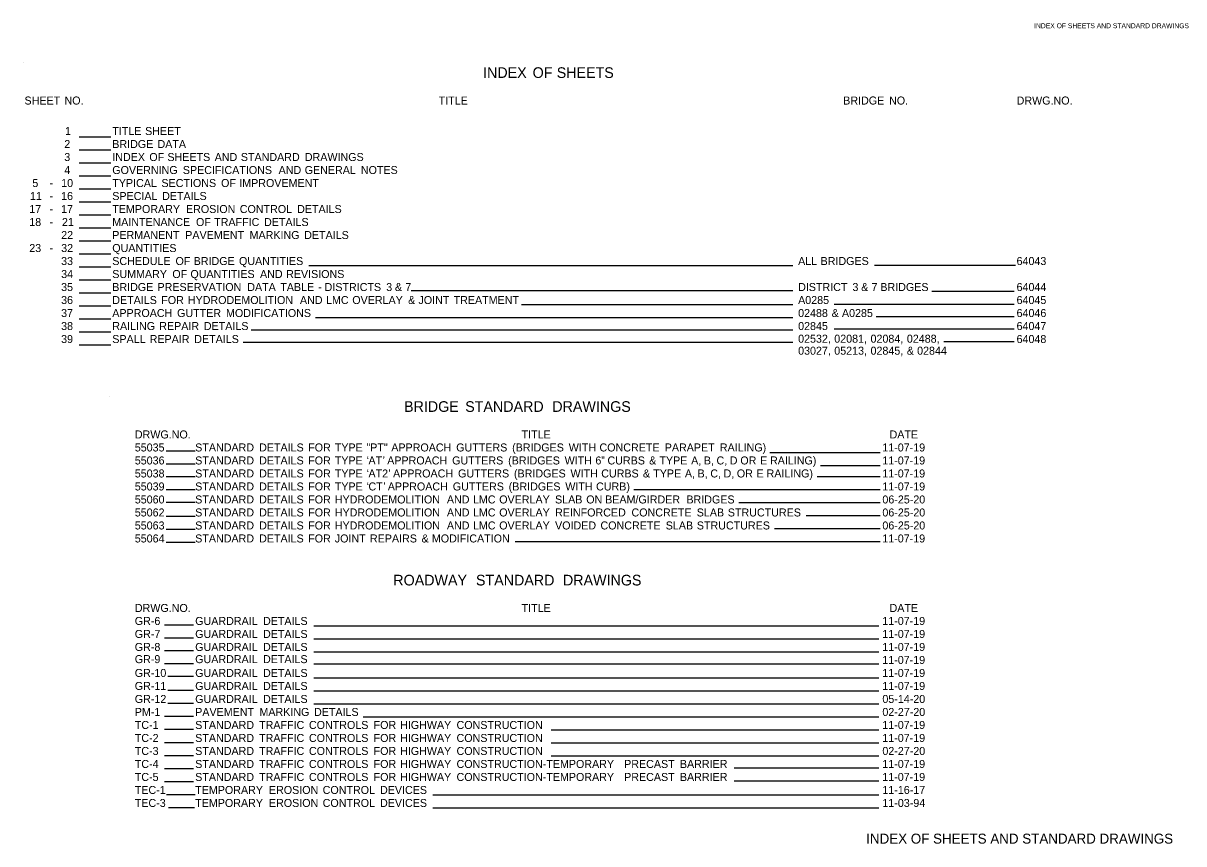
# Model space of a CAD drawing. Extents: x 1930541 to 1931933, y 596452 to 598974.
import ezdxf

# ---------------------------------------------------------------- set-up
doc = ezdxf.new("R2010")
doc.units = 0
for name, color, linetype in [('Default', 7, 'Continuous'), ('R_Border', 7, 'Continuous'), ('R_Border Prem', 7, 'Continuous')]:
    doc.layers.add(name, color=color, linetype=linetype)

msp = doc.modelspace()

# ---------------------------------------------------------------- linework, layer by layer
at = {"layer": 'Default'}
for p, q in [((1930540.8, 598926.7), (1930540.8, 598926.7)), ((1930607.9, 598837.7), (1930646.1, 598837.7)), ((1930607.9, 598822.1), (1930646.1, 598822.1)), ((1930607.9, 598806.5), (1930646.1, 598806.5)), ((1930607.9, 598790.9), (1930646.1, 598790.9)), ((1930607.9, 598775.3), (1930646.1, 598775.3)), ((1930607.9, 598759.7), (1930646.1, 598759.7)), ((1930607.9, 598744.1), (1930646.1, 598744.1)), ((1930607.9, 598728.5), (1930646.1, 598728.5)), ((1930607.9, 598712.9), (1930646.1, 598712.9)), ((1930607.9, 598697.3), (1930646.1, 598697.3)), ((1930607.9, 598681.7), (1930646.1, 598681.7)), ((1931464.1, 598682.7), (1930883.6, 598682.7)), ((1931731.5, 598683), (1931562.4, 598683)), ((1930607.9, 598666.1), (1930646.1, 598666.1)), ((1930607.9, 598650.5), (1930646.1, 598650.5)), ((1931464.1, 598652.8), (1931006.3, 598652.8)), ((1931729.7, 598651.8), (1931631.2, 598651.8)), ((1931464.1, 598635.9), (1931138.6, 598635.9)), ((1931729.7, 598636.2), (1931514, 598636.2)), ((1930607.9, 598634.9), (1930646.1, 598634.9)), ((1930607.9, 598619.3), (1930646.1, 598619.3)), ((1931464.1, 598620.3), (1930891.7, 598620.3)), ((1931729.7, 598621.4), (1931564.2, 598621.4)), ((1930607.9, 598603.7), (1930646.1, 598603.7)), ((1931464.1, 598605.5), (1930814.4, 598605.5)), ((1931729.7, 598606.6), (1931514, 598606.6)), ((1930607.9, 598588.1), (1930646.1, 598588.1)), ((1931464.1, 598590.7), (1930804.8, 598590.7)), ((1931729.7, 598591.7), (1931645.5, 598591.7)), ((1930644.2, 598526), (1930644.2, 598526)), ((1930747.2, 598460.3), (1930712.5, 598460.3)), ((1931436.8, 598458.9), (1931569.1, 598458.9)), ((1930747.2, 598444.9), (1930712.5, 598444.9)), ((1931497.4, 598443.3), (1931569.1, 598443.3)), ((1930747.2, 598429.5), (1930712.5, 598429.5)), ((1931493.3, 598430), (1931569.1, 598430)), ((1930747.2, 598414.1), (1930712.5, 598414.1)), ((1931273.4, 598414.4), (1931569.1, 598414.4)), ((1930747.2, 598398.7), (1930712.5, 598398.7)), ((1931399.5, 598398.8), (1931569.1, 598398.8)), ((1930747.2, 598382.1), (1930712.5, 598382.1)), ((1931480.1, 598383.2), (1931569.1, 598383.2)), ((1930747.2, 598366.3), (1930712.5, 598366.3)), ((1931442.3, 598367.6), (1931569.1, 598367.6)), ((1930747.2, 598350.7), (1930712.5, 598350.7)), ((1931131.2, 598352), (1931569.1, 598352)), ((1930745, 598251.4), (1930710.2, 598251.4)), ((1930889.7, 598250.7), (1931567.4, 598250.7)), ((1930745, 598236), (1930710.2, 598236)), ((1930889.7, 598235.1), (1931567.4, 598235.1)), ((1930745, 598220.6), (1930710.2, 598220.6)), ((1930889.7, 598219.5), (1931567.4, 598219.5)), ((1930745, 598205.2), (1930710.2, 598205.2)), ((1930889.7, 598205), (1931567.4, 598205)), ((1930745, 598189.8), (1930714.2, 598189.8)), ((1930889.7, 598188.3), (1931567.4, 598188.3)), ((1930745, 598173.2), (1930714.2, 598173.2)), ((1930889.7, 598172.7), (1931567.4, 598172.7)), ((1930745, 598157.4), (1930714.2, 598157.4)), ((1930889.7, 598157.1), (1931567.4, 598157.1)), ((1930745, 598141.8), (1930710.2, 598141.8)), ((1930948.6, 598141.5), (1931567.4, 598141.5)), ((1930745, 598126.2), (1930710.2, 598126.2)), ((1931174.1, 598125.9), (1931567.4, 598125.9)), ((1930745, 598110.5), (1930710.2, 598110.5)), ((1931020.8, 598115), (1931020.8, 598115)), ((1931174.1, 598110.3), (1931567.4, 598110.3)), ((1930745, 598094.9), (1930710.2, 598094.9)), ((1931174.1, 598094.7), (1931567.4, 598094.7)), ((1930745, 598079.2), (1930710.2, 598079.2)), ((1931393.9, 598080.3), (1931567.4, 598080.3)), ((1930745, 598063.5), (1930710.2, 598063.5)), ((1931393.9, 598064.7), (1931567.4, 598064.7)), ((1930747.3, 598047.9), (1930712.6, 598047.9)), ((1931032.4, 598047.9), (1931567.4, 598047.9)), ((1930746.4, 598032.2), (1930715, 598032.2)), ((1931032.4, 598032.3), (1931567.4, 598032.3))]:
    msp.add_line(p, q, dxfattribs=at)

# ---------------------------------------------------------------- texts
for s, height, p in [('INDEX', 12.8, (1931092.6, 598908.2)), (' OF', 12.8, (1931147.3, 598908.2)), (' SHEETS', 12.8, (1931176.2, 598908.2)), ('SHEET', 9.6, (1930542.4, 598876.3)), (' NO.', 9.6, (1930586.8, 598876.3)), ('TITLE', 9.6, (1931039.3, 598876.3)), ('BRIDGE', 9.6, (1931524.7, 598876.3)), (' NO.', 9.6, (1931576.2, 598876.3)), ('DRWG.NO.', 9.6, (1931732.8, 598876.3)), ('1', 9.6, (1930591, 598839.7)), ('TITLE', 9.6, (1930647.7, 598839.7)), (' SHEET', 9.6, (1930683.5, 598839.7)), ('2', 9.6, (1930590.1, 598824.1)), ('BRIDGE', 9.6, (1930647.7, 598824.1)), (' DATA', 9.6, (1930698.4, 598824.1)), ('3', 9.6, (1930590.1, 598808.5)), ('INDEX', 9.6, (1930647.7, 598808.5)), (' OF', 9.6, (1930688.6, 598808.5)), (' SHEETS', 9.6, (1930710.3, 598808.5)), (' AND', 9.6, (1930767, 598808.5)), (' STANDARD', 9.6, (1930798.4, 598808.5)), (' DRAWINGS', 9.6, (1930875.2, 598808.5)), ('4', 9.6, (1930590.1, 598792.9)), ('GOVERNING', 9.6, (1930647.7, 598792.9)), (' SPECIFICATIONS', 9.6, (1930728.8, 598792.9)), (' AND', 9.6, (1930843.7, 598792.9)), (' GENERAL', 9.6, (1930875, 598792.9)), (' NOTES', 9.6, (1930942.4, 598792.9)), ('5', 9.6, (1930551.8, 598777.3)), ('-', 9.6, (1930572.4, 598777.3)), ('10', 9.6, (1930586.4, 598777.3)), ('TYPICAL', 9.6, (1930647.7, 598777.3)), (' SECTIONS', 9.6, (1930703.1, 598777.3)), (' OF', 9.6, (1930774.7, 598777.3)), (' IMPROVEMENT', 9.6, (1930796.5, 598777.3)), ('11', 9.6, (1930549, 598761.7)), ('-', 9.6, (1930572.4, 598761.7)), ('16', 9.6, (1930586.3, 598761.7)), ('SPECIAL', 9.6, (1930647.7, 598761.7)), (' DETAILS', 9.6, (1930703.9, 598761.7)), ('17', 9.6, (1930548.1, 598746.1)), ('-', 9.6, (1930572.4, 598746.1)), ('17', 9.6, (1930586.3, 598746.1)), ('TEMPORARY', 9.6, (1930647.7, 598746.1)), (' EROSION', 9.6, (1930732.6, 598746.1)), (' CONTROL', 9.6, (1930797.1, 598746.1)), (' DETAILS', 9.6, (1930865.9, 598746.1)), ('18', 9.6, (1930548.1, 598730.5)), ('-', 9.6, (1930572.4, 598730.5)), ('21', 9.6, (1930587.3, 598730.5)), ('MAINTENANCE', 9.6, (1930647.7, 598730.5)), (' OF', 9.6, (1930744.6, 598730.5)), (' TRAFFIC', 9.6, (1930766.4, 598730.5)), (' DETAILS', 9.6, (1930826.2, 598730.5)), ('22', 9.6, (1930586.4, 598714.9)), ('PERMANENT', 9.6, (1930647.7, 598714.9)), (' PAVEMENT', 9.6, (1930731.7, 598714.9)), (' MARKING', 9.6, (1930808.9, 598714.9)), (' DETAILS', 9.6, (1930874.4, 598714.9)), ('23', 9.6, (1930548.1, 598699.3)), ('32', 9.6, (1930586.4, 598699.3)), ('QUANTITIES', 9.6, (1930647.7, 598699.3)), ('-', 9.6, (1930572.4, 598699.3)), ('33', 9.6, (1930586.3, 598683.7)), ('SCHEDULE', 9.6, (1930647.7, 598683.7)), (' OF', 9.6, (1930720, 598683.7)), (' BRIDGE', 9.6, (1930741.8, 598683.7)), (' QUANTITIES', 9.6, (1930796.2, 598683.7)), ('ALL', 9.6, (1931470.6, 598683.7)), (' BRIDGES', 9.6, (1931494, 598683.7)), ('64043', 9.6, (1931732.7, 598683.7)), ('34', 9.6, (1930586.4, 598668.1)), ('SUMMARY', 9.6, (1930647.7, 598668.1)), (' OF', 9.6, (1930716.2, 598668.1)), (' QUANTITIES', 9.6, (1930737.9, 598668.1)), (' AND', 9.6, (1930821.4, 598668.1)), (' REVISIONS', 9.6, (1930852.7, 598668.1)), ('35', 9.6, (1930586.3, 598652.5)), ('BRIDGE', 9.6, (1930647.7, 598652.5)), (' PRESERVATION', 9.6, (1930698.4, 598652.5)), (' DATA', 9.6, (1930806.1, 598652.5)), (' TABLE', 9.6, (1930845.7, 598652.5)), (' -', 9.6, (1930891.2, 598652.5)), (' DISTRICTS', 9.6, (1930898.9, 598652.5)), (' 3', 9.6, (1930972.8, 598652.5)), (' &', 9.6, (1930983.3, 598652.5)), (' 7', 9.6, (1930995.7, 598652.5)), ('DISTRICT', 9.6, (1931470.6, 598652.5)), (' 3', 9.6, (1931532.2, 598652.5)), (' &', 9.6, (1931542.7, 598652.5)), (' 7', 9.6, (1931555.1, 598652.5)), (' BRIDGES', 9.6, (1931565.7, 598652.5)), ('64044', 9.6, (1931732.7, 598652.5)), ('36', 9.6, (1930586.3, 598636.9)), ('DETAILS', 9.6, (1930647.7, 598636.9)), (' FOR', 9.6, (1930702.9, 598636.9)), (' HYDRODEMOLITION', 9.6, (1930734.8, 598636.9)), (' AND', 9.6, (1930869.3, 598636.9)), (' LMC', 9.6, (1930900.6, 598636.9)), (' OVERLAY', 9.6, (1930932.1, 598636.9)), (' &', 9.6, (1930999.1, 598636.9)), (' JOINT', 9.6, (1931011.5, 598636.9)), (' TREATMENT', 9.6, (1931053.7, 598636.9)), ('A0285', 9.6, (1931470.6, 598636.9)), ('64045', 9.6, (1931732.7, 598636.9)), ('37', 9.6, (1930586.3, 598621.3)), ('APPROACH', 9.6, (1930647.7, 598621.3)), (' GUTTER', 9.6, (1930721.9, 598621.3)), (' MODIFICATIONS', 9.6, (1930780.6, 598621.3)), ('02488', 9.6, (1931470.6, 598621.3)), (' &', 9.6, (1931507.3, 598621.3)), (' A0285', 9.6, (1931519.6, 598621.3)), ('64046', 9.6, (1931732.7, 598621.3)), ('38', 9.6, (1930586.3, 598605.7)), ('RAILING', 9.6, (1930647.7, 598605.7)), (' REPAIR', 9.6, (1930700.5, 598605.7)), (' DETAILS', 9.6, (1930754, 598605.7)), ('02845', 9.6, (1931470.6, 598605.7)), ('64047', 9.6, (1931732.7, 598605.7)), ('39', 9.6, (1930586.3, 598590.1)), ('SPALL', 9.6, (1930647.7, 598590.1)), (' REPAIR', 9.6, (1930689, 598590.1)), (' DETAILS', 9.6, (1930742.5, 598590.1)), ('02532,', 9.6, (1931470.6, 598590.5)), (' 02081,', 9.6, (1931510.4, 598590.5)), (' 02084,', 9.6, (1931553.9, 598590.5)), (' 02488,', 9.6, (1931597.5, 598590.5)), ('64048', 9.6, (1931732.7, 598590.1)), ('03027,', 9.6, (1931470.6, 598576.1)), (' 05213,', 9.6, (1931510.4, 598576.1)), (' 02845,', 9.6, (1931553.9, 598576.1)), (' &', 9.6, (1931597.5, 598576.1)), (' 02844', 9.6, (1931609.8, 598576.1))]:
    msp.add_text(s, height=height, rotation=360, dxfattribs=at).set_placement(p)
for s, height, p in [('BRIDGE', 12.8, (1930997.8, 598507.5)), (' STANDARD', 12.8, (1931066.4, 598507.5)), (' DRAWINGS', 12.8, (1931170.9, 598507.5)), ('DRWG.NO.', 9.6, (1930674.8, 598475.6)), ('TITLE', 9.6, (1931138.8, 598475.6)), ('DATE', 9.6, (1931580.3, 598475.6)), ('55035', 9.6, (1930674.7, 598460)), ('STANDARD', 9.6, (1930747.2, 598460)), (' DETAILS', 9.6, (1930820.3, 598460)), (' FOR', 9.6, (1930879.2, 598460)), (' TYPE', 9.6, (1930911.1, 598460)), (' "PT"', 9.6, (1930949.1, 598460)), (' APPROACH', 9.6, (1930978.9, 598460)), (' GUTTERS', 9.6, (1931056.8, 598460)), (' (BRIDGES', 9.6, (1931123.9, 598460)), (' WITH', 9.6, (1931191.8, 598460)), (' CONCRETE', 9.6, (1931228.7, 598460)), (' PARAPET', 9.6, (1931307, 598460)), (' RAILING)', 9.6, (1931373.1, 598460)), ('11-07-19', 9.6, (1931571.6, 598460)), ('55036', 9.6, (1930674.7, 598444.4)), ('STANDARD', 9.6, (1930747.2, 598444.4)), (' DETAILS', 9.6, (1930820.3, 598444.4)), (' FOR', 9.6, (1930879.2, 598444.4)), (' TYPE', 9.6, (1930911.1, 598444.4)), ('‘', 9.6, (1930952.8, 598444.4)), ('AT', 9.6, (1930955.1, 598444.4)), ('’', 9.6, (1930971.9, 598444.4)), (' APPROACH', 9.6, (1930974, 598444.4)), (' GUTTERS', 9.6, (1931051.9, 598444.4)), (' (BRIDGES', 9.6, (1931119.1, 598444.4)), (' WITH', 9.6, (1931186.9, 598444.4)), (' 6', 9.6, (1931223.8, 598444.4)), ('”', 9.6, (1931234.4, 598444.4)), (' CURBS', 9.6, (1931238.3, 598444.4)), (' &', 9.6, (1931288.3, 598444.4)), (' TYPE', 9.6, (1931300.6, 598444.4)), (' A,', 9.6, (1931338.7, 598444.4)), (' B,', 9.6, (1931353.9, 598444.4)), (' C,', 9.6, (1931369.1, 598444.4)), (' D', 9.6, (1931385, 598444.4)), (' OR', 9.6, (1931397.7, 598444.4)), (' E', 9.6, (1931421.4, 598444.4)), (' RAILING)', 9.6, (1931433.3, 598444.4)), ('11-07-19', 9.6, (1931571.6, 598444.4)), ('55038', 9.6, (1930674.7, 598428.8)), ('STANDARD', 9.6, (1930747.2, 598428.8)), (' DETAILS', 9.6, (1930820.3, 598428.8)), (' FOR', 9.6, (1930879.2, 598428.8)), (' TYPE', 9.6, (1930911.1, 598428.8)), ('‘', 9.6, (1930952.8, 598428.8)), ('AT2', 9.6, (1930955.1, 598428.8)), ('’', 9.6, (1930978.9, 598428.8)), (' APPROACH', 9.6, (1930981, 598428.8)), (' GUTTERS', 9.6, (1931059, 598428.8)), (' (BRIDGES', 9.6, (1931126.1, 598428.8)), (' WITH', 9.6, (1931193.9, 598428.8)), (' CURBS', 9.6, (1931230.8, 598428.8)), (' &', 9.6, (1931280.8, 598428.8)), (' TYPE', 9.6, (1931293.2, 598428.8)), (' A,', 9.6, (1931331.2, 598428.8)), (' B,', 9.6, (1931346.4, 598428.8)), (' C,', 9.6, (1931361.7, 598428.8)), (' D,', 9.6, (1931377.6, 598428.8)), (' OR', 9.6, (1931393.5, 598428.8)), (' E', 9.6, (1931417.2, 598428.8)), (' RAILING)', 9.6, (1931429.2, 598428.8)), ('11-07-19', 9.6, (1931571.6, 598428.8)), ('55039', 9.6, (1930674.7, 598413.2)), ('STANDARD', 9.6, (1930747.2, 598413.2)), (' DETAILS', 9.6, (1930820.3, 598413.2)), (' FOR', 9.6, (1930879.2, 598413.2)), (' TYPE', 9.6, (1930911.1, 598413.2)), ('‘', 9.6, (1930952.8, 598413.2)), ('CT', 9.6, (1930955.1, 598413.2)), ('’', 9.6, (1930972.7, 598413.2)), (' APPROACH', 9.6, (1930974.7, 598413.2)), (' GUTTERS', 9.6, (1931052.7, 598413.2)), (' (BRIDGES', 9.6, (1931119.8, 598413.2)), (' WITH', 9.6, (1931187.7, 598413.2)), (' CURB)', 9.6, (1931224.6, 598413.2)), ('11-07-19', 9.6, (1931571.6, 598413.2)), ('55060', 9.6, (1930674.7, 598397.6)), ('STANDARD', 9.6, (1930747.2, 598397.6)), (' DETAILS', 9.6, (1930820.3, 598397.6)), (' FOR', 9.6, (1930879.2, 598397.6)), (' HYDRODEMOLITION', 9.6, (1930911.1, 598397.6)), (' AND', 9.6, (1931045.6, 598397.6)), (' LMC', 9.6, (1931076.9, 598397.6)), (' OVERLAY', 9.6, (1931108.4, 598397.6)), (' SLAB', 9.6, (1931175.4, 598397.6)), (' ON', 9.6, (1931212.8, 598397.6)), (' BEAM/GIRDER', 9.6, (1931235.5, 598397.6)), (' BRIDGES', 9.6, (1931333, 598397.6)), ('06-25-20', 9.6, (1931571.7, 598397.6)), ('55062', 9.6, (1930674.7, 598382)), ('STANDARD', 9.6, (1930747.2, 598382)), (' DETAILS', 9.6, (1930820.3, 598382)), (' FOR', 9.6, (1930879.2, 598382)), (' HYDRODEMOLITION', 9.6, (1930911.1, 598382)), (' AND', 9.6, (1931045.6, 598382)), (' LMC', 9.6, (1931076.9, 598382)), (' OVERLAY', 9.6, (1931108.4, 598382)), (' REINFORCED', 9.6, (1931175.4, 598382)), (' CONCRETE', 9.6, (1931267.1, 598382)), (' SLAB', 9.6, (1931345.4, 598382)), (' STRUCTURES', 9.6, (1931382.7, 598382)), ('06-25-20', 9.6, (1931571.7, 598382)), ('55063', 9.6, (1930674.7, 598366.4)), ('STANDARD', 9.6, (1930747.2, 598366.4)), (' DETAILS', 9.6, (1930820.3, 598366.4)), (' FOR', 9.6, (1930879.2, 598366.4)), (' HYDRODEMOLITION', 9.6, (1930911.1, 598366.4)), (' AND', 9.6, (1931045.6, 598366.4)), (' LMC', 9.6, (1931076.9, 598366.4)), (' OVERLAY', 9.6, (1931108.4, 598366.4)), (' VOIDED', 9.6, (1931175.4, 598366.4)), (' CONCRETE', 9.6, (1931229.9, 598366.4)), (' SLAB', 9.6, (1931308.2, 598366.4)), (' STRUCTURES', 9.6, (1931345.5, 598366.4)), ('06-25-20', 9.6, (1931571.7, 598366.4)), ('55064', 9.6, (1930674.7, 598350.8)), ('STANDARD', 9.6, (1930747.2, 598350.8)), (' DETAILS', 9.6, (1930820.3, 598350.8)), (' FOR', 9.6, (1930879.2, 598350.8)), (' JOINT', 9.6, (1930911.1, 598350.8)), (' REPAIRS', 9.6, (1930953.3, 598350.8)), (' &', 9.6, (1931015.2, 598350.8)), (' MODIFICATION', 9.6, (1931027.6, 598350.8)), ('11-07-19', 9.6, (1931571.6, 598350.8)), ('ROADWAY', 12.8, (1930984.9, 598299.2)), (' STANDARD', 12.8, (1931079.3, 598299.2)), (' DRAWINGS', 12.8, (1931183.7, 598299.2)), ('DRWG.NO.', 9.6, (1930674.8, 598267.4)), ('TITLE', 9.6, (1931138.8, 598267.4)), ('DATE', 9.6, (1931580.3, 598267.4)), ('GR-6', 9.6, (1930674.7, 598251.8)), ('GUARDRAIL', 9.6, (1930747.2, 598251.8)), (' DETAILS', 9.6, (1930825, 598251.8)), ('11-07-19', 9.6, (1931571.6, 598251.8)), ('GR-7', 9.6, (1930674.7, 598236.2)), ('GUARDRAIL', 9.6, (1930747.2, 598236.2)), (' DETAILS', 9.6, (1930825, 598236.2)), ('11-07-19', 9.6, (1931571.6, 598236.2)), ('GR-8', 9.6, (1930674.7, 598220.6)), ('GUARDRAIL', 9.6, (1930747.2, 598220.6)), (' DETAILS', 9.6, (1930825, 598220.6)), ('11-07-19', 9.6, (1931571.6, 598220.6)), ('GR-9', 9.6, (1930674.7, 598206)), ('GUARDRAIL', 9.6, (1930747.2, 598206)), (' DETAILS', 9.6, (1930825, 598206)), ('11-07-19', 9.6, (1931571.6, 598205)), ('GR-10', 9.6, (1930674.7, 598189.4)), ('GUARDRAIL', 9.6, (1930747.2, 598189.4)), (' DETAILS', 9.6, (1930825, 598189.4)), ('11-07-19', 9.6, (1931571.6, 598189.4)), ('GR-11', 9.6, (1930674.7, 598173.8)), ('GUARDRAIL', 9.6, (1930747.2, 598173.8)), (' DETAILS', 9.6, (1930825, 598173.8)), ('11-07-19', 9.6, (1931571.6, 598173.8)), ('GR-12', 9.6, (1930674.7, 598158.2)), ('GUARDRAIL', 9.6, (1930747.2, 598158.2)), (' DETAILS', 9.6, (1930825, 598158.2)), ('05-14-20', 9.6, (1931571.7, 598158.2)), ('PM-1', 9.6, (1930674.7, 598142.6)), ('PAVEMENT', 9.6, (1930747.2, 598142.6)), (' MARKING', 9.6, (1930820.7, 598142.6)), (' DETAILS', 9.6, (1930886.2, 598142.6)), ('02-27-20', 9.6, (1931571.7, 598142.6)), ('TC-1', 9.6, (1930674.7, 598127)), ('STANDARD', 9.6, (1930747.2, 598127)), (' TRAFFIC', 9.6, (1930820.3, 598127)), (' CONTROLS', 9.6, (1930880.1, 598127)), (' FOR', 9.6, (1930957.7, 598127)), (' HIGHWAY', 9.6, (1930989.5, 598127)), (' CONSTRUCTION', 9.6, (1931057.2, 598127)), ('11-07-19', 9.6, (1931571.6, 598127)), ('TC-2', 9.6, (1930674.7, 598111.4)), ('STANDARD', 9.6, (1930747.2, 598111.4)), (' TRAFFIC', 9.6, (1930820.3, 598111.4)), (' CONTROLS', 9.6, (1930880.1, 598111.4)), (' FOR', 9.6, (1930957.7, 598111.4)), (' HIGHWAY', 9.6, (1930989.5, 598111.4)), (' CONSTRUCTION', 9.6, (1931057.2, 598111.4)), ('11-07-19', 9.6, (1931571.6, 598111.4)), ('TC-3', 9.6, (1930674.7, 598095.8)), ('STANDARD', 9.6, (1930747.2, 598095.8)), (' TRAFFIC', 9.6, (1930820.3, 598095.8)), (' CONTROLS', 9.6, (1930880.1, 598095.8)), (' FOR', 9.6, (1930957.7, 598095.8)), (' HIGHWAY', 9.6, (1930989.5, 598095.8)), (' CONSTRUCTION', 9.6, (1931057.2, 598095.8)), ('02-27-20', 9.6, (1931571.7, 598095.8)), ('TC-4', 9.6, (1930674.7, 598080.2)), ('STANDARD', 9.6, (1930747.2, 598080.2)), (' TRAFFIC', 9.6, (1930820.3, 598080.2)), (' CONTROLS', 9.6, (1930880.1, 598080.2)), (' FOR', 9.6, (1930957.7, 598080.2)), (' HIGHWAY', 9.6, (1930989.5, 598080.2)), (' CONSTRUCTION-TEMPORARY', 9.6, (1931057.2, 598080.2)), (' PRECAST', 9.6, (1931258.3, 598080.2)), (' BARRIER', 9.6, (1931325.2, 598080.2)), ('11-07-19', 9.6, (1931571.6, 598080.2)), ('TC-5', 9.6, (1930674.7, 598064.6)), ('STANDARD', 9.6, (1930747.2, 598064.6)), (' TRAFFIC', 9.6, (1930820.3, 598064.6)), (' CONTROLS', 9.6, (1930880.1, 598064.6)), (' FOR', 9.6, (1930957.7, 598064.6)), (' HIGHWAY', 9.6, (1930989.5, 598064.6)), (' CONSTRUCTION-TEMPORARY', 9.6, (1931057.2, 598064.6)), (' PRECAST', 9.6, (1931258.3, 598064.6)), (' BARRIER', 9.6, (1931325.2, 598064.6)), ('11-07-19', 9.6, (1931571.6, 598064.6)), ('TEC-1', 9.6, (1930674.7, 598049)), ('TEMPORARY', 9.6, (1930747.2, 598049)), (' EROSION', 9.6, (1930832.1, 598049)), (' CONTROL', 9.6, (1930896.6, 598049)), (' DEVICES', 9.6, (1930965.4, 598049)), ('11-16-17', 9.6, (1931571.7, 598049)), ('TEC-3', 9.6, (1930674.7, 598033.4)), ('TEMPORARY', 9.6, (1930747.2, 598033.4)), (' EROSION', 9.6, (1930832.1, 598033.4)), (' CONTROL', 9.6, (1930896.6, 598033.4)), (' DEVICES', 9.6, (1930965.4, 598033.4)), ('11-03-94', 9.6, (1931571.7, 598033.4))]:
    msp.add_text(s, height=height, dxfattribs=at).set_placement(p)
at = {"layer": 'R_Border'}
msp.add_text('INDEX OF SHEETS AND STANDARD DRAWINGS', height=12, rotation=360, dxfattribs=at).set_placement((1931552.3, 597989.4))
at = {"layer": 'R_Border Prem'}
msp.add_text('INDEX OF SHEETS AND STANDARD DRAWINGS', height=5.862, rotation=360, dxfattribs=at).set_placement((1931753.8, 598967.9))

doc.saveas('drawing.dxf')
